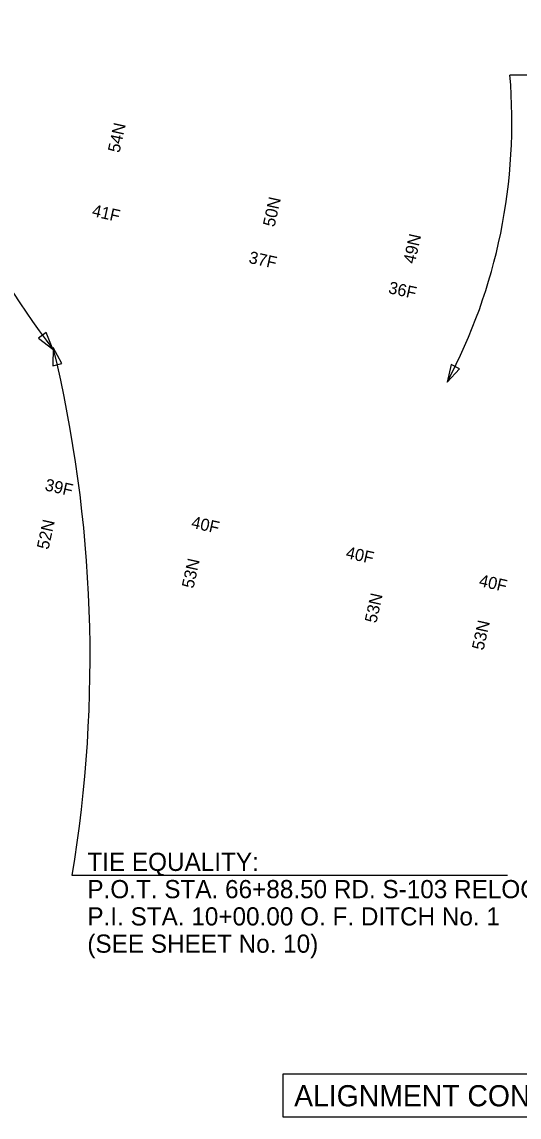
# Model space of a CAD drawing. Extents: x 1964849 to 1967422, y 1116563 to 1122211.
# Drawn here: x 1967005.5 to 1967169.6, y 1118230.2 to 1118591.7 of the extents above; entities that cross this region are included whole.
import ezdxf

# ---------------------------------------------------------------- set-up
doc = ezdxf.new("R2010")
doc.units = 0
for name, color, linetype in [('RD_HC_Data', 7, 'Continuous'), ('RD_PD_TX_CstnLmt', 7, 'Continuous'), ('RD_Sketch1', 7, 'Continuous'), ('RD_TX_Drainage', 7, 'Continuous'), ('RD_TX_Misc1', 7, 'Continuous')]:
    doc.layers.add(name, color=color, linetype=linetype)

msp = doc.modelspace()

# ---------------------------------------------------------------- linework, layer by layer
at = {"layer": 'RD_HC_Data'}
msp.add_line((1967165.81, 1118309.94), (1967022.08, 1118309.94), dxfattribs=at)
msp.add_lwpolyline([(1967018.71, 1118478.94), (1967015.84, 1118484.22), (1967015.69, 1118478.22)], close=True, dxfattribs=at)
msp.add_arc((1966589.37, 1118381.72), 438.62, 350.5812, 13.5141, dxfattribs=at)
at = {"layer": 'RD_Sketch1'}
msp.add_lwpolyline([(1967091.71, 1118244.43), (1967392.13, 1118244.43), (1967392.13, 1118230.17), (1967091.71, 1118230.17)], close=True, dxfattribs=at)
at = {"layer": 'RD_TX_Drainage'}
msp.add_lwpolyline([(1967010.97, 1118487.32), (1967015.73, 1118483.67), (1967013.43, 1118489.21)], close=True, dxfattribs=at)
msp.add_arc((1967238.28, 1118654.56), 280.59, 192.9351, 217.5188, dxfattribs=at)
at = {"layer": 'RD_TX_Misc1'}
msp.add_line((1967333.2, 1118574.21), (1967166.6, 1118574.21), dxfattribs=at)
msp.add_lwpolyline([(1967147.24, 1118478.67), (1967145.89, 1118472.82), (1967149.98, 1118477.21)], close=True, dxfattribs=at)
msp.add_arc((1966984.14, 1118558.66), 183.12, 332.0444, 4.8712, dxfattribs=at)

# ---------------------------------------------------------------- texts
at = {"layer": 'RD_HC_Data'}
for s, p in [('TIE EQUALITY:', (1967027.08, 1118311.44)), ('P.O.T. STA. 66+88.50 RD. S-103 RELOC. =', (1967027.08, 1118302.44)), ('P.I. STA. 10+00.00 O. F. DITCH No. 1', (1967027.08, 1118293.44)), ('(SEE SHEET No. 10)', (1967027.08, 1118284.44))]:
    msp.add_text(s, height=6, dxfattribs=at).set_placement(p)
at = {"layer": 'RD_PD_TX_CstnLmt'}
for s, p in [('41F', (1967028.37, 1118527.66)), ('37F', (1967080.13, 1118512.21)), ('36F', (1967126.24, 1118502.23)), ('39F', (1967012.82, 1118437.13)), ('40F', (1967061.16, 1118424.76)), ('40F', (1967112.18, 1118414.76)), ('40F', (1967156.15, 1118405.52))]:
    msp.add_text(s, height=4, rotation=347.4724, dxfattribs=at).set_placement(p)
at = {"layer": 'RD_Sketch1'}
msp.add_text('ALIGNMENT CONTROL CAN BE FOUND ON REFERENCE SHEET', height=7, dxfattribs=at).set_placement((1967095.36, 1118233.72))
at = {"layer": 'RD_TX_Drainage'}
for s, p in [('54N', (1967037.68, 1118548.33)), ('50N', (1967088.88, 1118523.85)), ('49N', (1967135.2, 1118511.67)), ('52N', (1967014.24, 1118417.34)), ('53N', (1967062.1, 1118404.5)), ('53N', (1967122.49, 1118393.05)), ('53N', (1967157.89, 1118384.1))]:
    msp.add_text(s, height=4, rotation=77.4724, dxfattribs=at).set_placement(p)

doc.saveas('drawing.dxf')
